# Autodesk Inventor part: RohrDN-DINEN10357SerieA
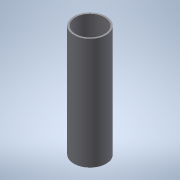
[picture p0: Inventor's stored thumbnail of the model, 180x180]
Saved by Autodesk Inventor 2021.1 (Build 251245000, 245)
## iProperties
RuleStatus: InUse
Created: 2020-09
Part Number: RohrDN-DINEN10357SerieA
Material: 1.4301
Document SubType Name: Modellierung
Designer: D.Rödiger
Mass: 15.7865 g
Surface Area: 213.644 cm^2
Volume: 15.7865 cm^3
Density: 1 g/cm^3
Sheet Metal Rule: 1.00mm R1.75
Sheet Metal Width: 0.000 mm
Sheet Metal Length: 0.000 mm
Sheet Metal Area: 0.000 mm^2
Appearance: Vorgabe
AfterDocNew0: formular_oeffnen
Länge: 100,000 mm
Bezeichnung: DN100
Variante: Rohr DN25
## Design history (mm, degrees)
sketch "Skizze9"
  geometry: C1 r 13 at (0, 0); C2 r 14.5 at (0, 0); 1 further point
  constraints: 2 centre point, 2 coincident
  dimensions: "DA" = 29 diameter of C2; "WS" = 1.5 radial gap between concentric circles of C2 C1
extrude "Extrusion1" new body sketch "Skizze9" taper "d28" = 0 deg; distance "Länge31" = 100 (= Länge)
node "Volumenkörper6"
other parameters: "Stärke" = 1 (derived), "KFaktor" = 4.4, "Biegeradius" = 1.75 (derived), "BreiteBiegungsfreistellung" = 0.32 (derived), "TiefeBiegungsfreistellung" = 0.5 (= 0.5 x Stärke), "GrößeEckenfreistellung" = 4 (= 4 x Stärke), "AbstandVerbindung" = 0.01, "MinimalRest" = 2 (= 2 x Stärke), "Übergangsradius" = 1.75 (= Biegeradius), "JacobiRadiusGröße" = 1.75 (= Biegeradius), "Abstandsgröße" = 1 (= Stärke), "Länge" = 100 [user parameter; used in 1 equation term]
